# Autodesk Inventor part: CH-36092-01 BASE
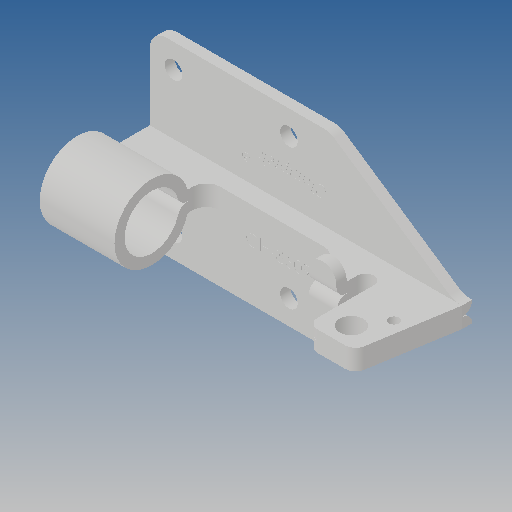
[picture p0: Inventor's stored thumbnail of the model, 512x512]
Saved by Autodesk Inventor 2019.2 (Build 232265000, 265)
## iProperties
Created: 2012-09
Part Number: CH-36092-01 BASE
Material: Ogólny
Document SubType Name: Modeling
Designer: CADENGINEERING4
Density: 1 g/cm^3
Appearance: Domyślna
Author: CADENGINEERING4
Revision Number: ÈÎºÎ
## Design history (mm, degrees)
feature "ÇÐ³ý-À­Éì3"
feature "ÇÐ³ý-À­Éì6"
node "Bryła1"
node "Bryła2"
